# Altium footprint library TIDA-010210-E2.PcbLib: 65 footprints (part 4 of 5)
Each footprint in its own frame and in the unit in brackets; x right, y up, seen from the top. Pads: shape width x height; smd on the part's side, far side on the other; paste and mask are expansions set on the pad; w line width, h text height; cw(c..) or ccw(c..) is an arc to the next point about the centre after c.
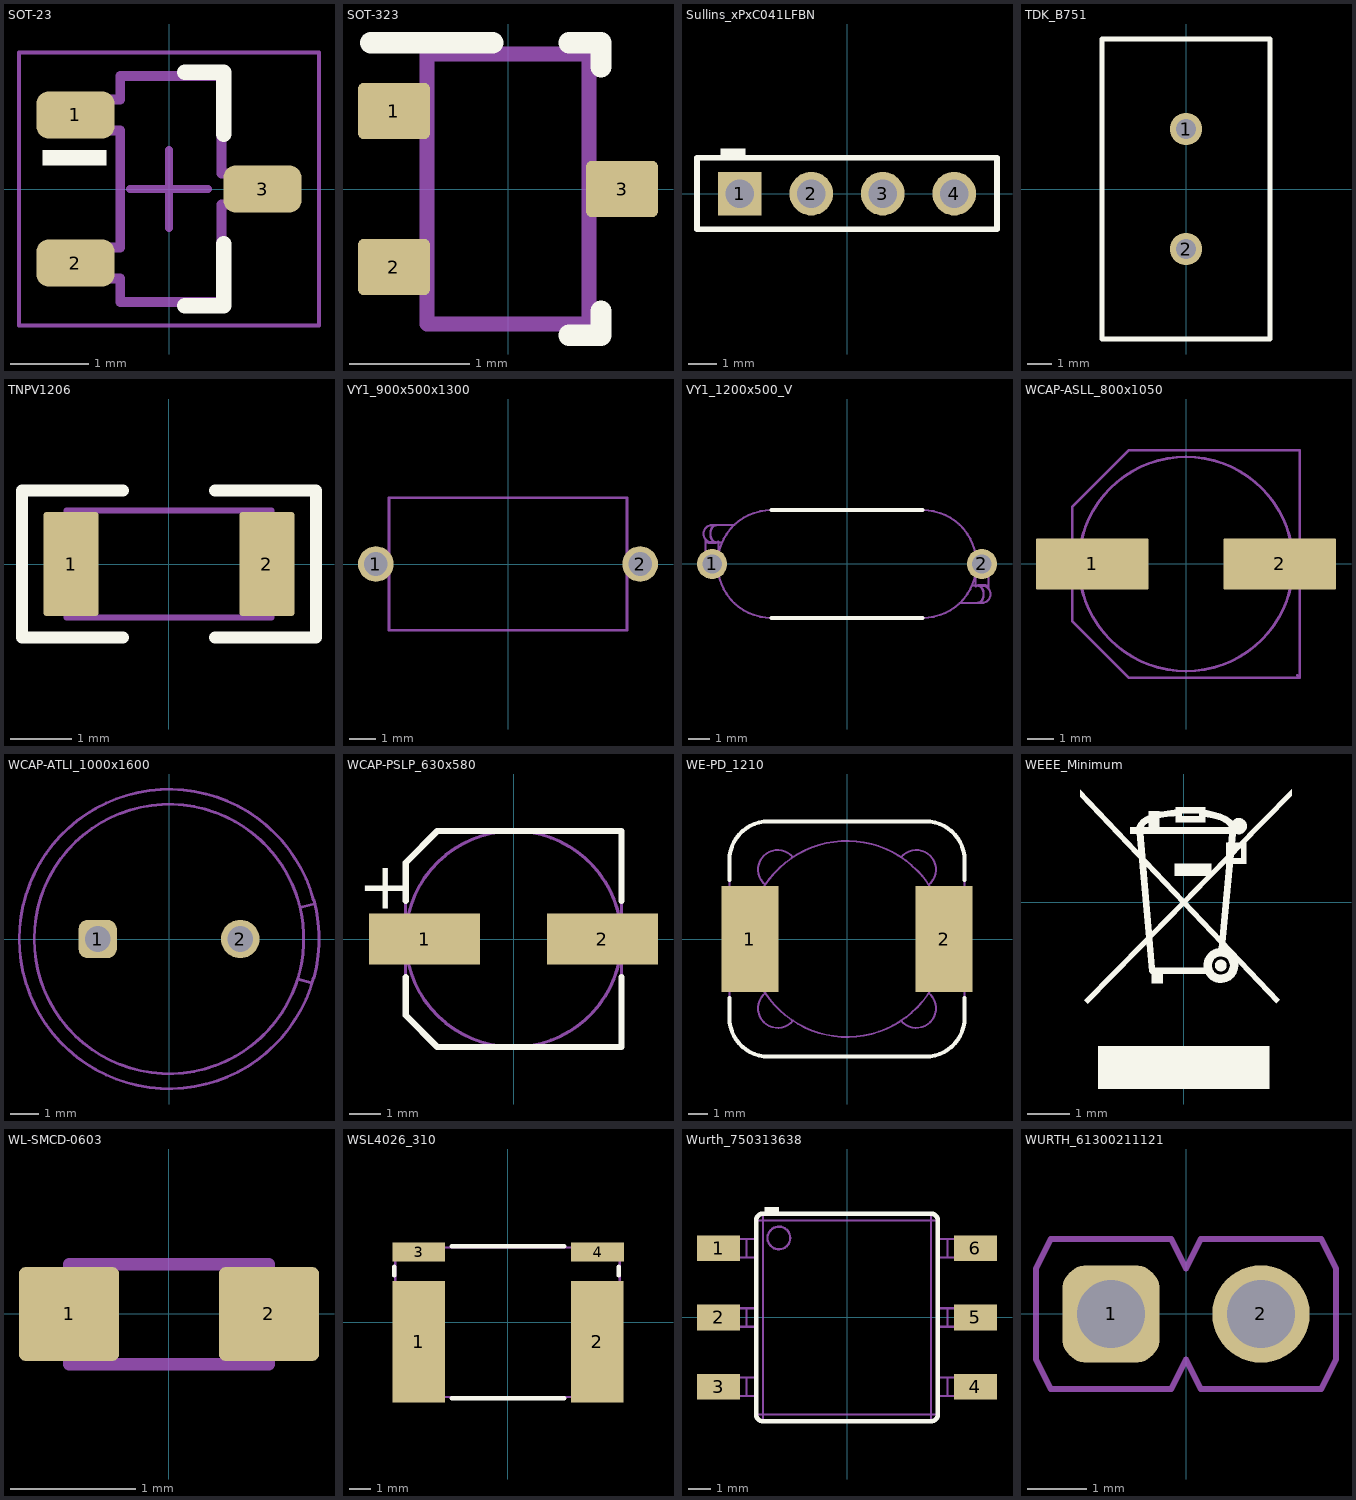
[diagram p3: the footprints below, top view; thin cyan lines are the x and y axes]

## SOT-23 [mm] "SOT23, 3-Leads, Body 2.9x1.3mm, Pitch 0.95mm, Lead Span 2.5mm, IPC Medium Density"
height 1.1
pads (3):
  rrect50% 1x0.6 smd: 1(-1.2,0.95) 2(-1.2,-0.95) 3(1.2,0)
Top Overlay:
  rectangle: -1.625,0.3 -0.8,0.5
  lines w0.2: 0.2,-1.5 0.7,-1.5 0.7,-0.7 ; 0.2,1.5 0.7,1.5 0.7,0.7
Mechanical 5:
  lines w0.127: -1.16,-1.15 -0.625,-1.15 -0.625,-1.45 0.675,-1.45 0.675,-0.2 1.21,-0.2 1.21,0.2 0.675,0.2 0.675,1.45 -0.625,1.45 -0.625,1.15 -1.16,1.15 -1.16,0.75 -0.625,0.75 -0.625,-0.75 -1.16,-0.75 -1.16,-1.15
  text ".Designator" at -0.175,1.225 h0.64
Mechanical 15:
  lines w0.05: -1.925,-1.75 -1.925,1.75 1.925,1.75 1.925,-1.75 -1.925,-1.75
  lines w0.1: -0.5,0 0.5,0 ; 0,-0.5 0,0.5
3D body "SW3dPS-sot-3p290x130ll237h100.STEP": height 1, standoff 0, extent -1.16,-1.45 1.21,1.45

## SOT-323 [mm] "Diodes Inc recommended land pattern.  2016-02-24"
height 1.1
pads (3):
  rrect21% 0.6x0.47 smd: 1(-0.95,0.65) 2(-0.95,-0.65) 3(0.95,0)
Top Overlay:
  lines w0.178: -1.143,1.219 -0.127,1.219 ; 0.508,-1.219 0.775,-1.219 0.775,-1.016 ; 0.508,1.219 0.775,1.219 0.775,1.016
Mechanical 5:
  lines w0.127: -1.125,-0.8 -1.125,-0.5 -0.975,-0.5 -0.935,-0.5 -0.884,-0.5 -0.725,-0.5 -0.675,-0.5 -0.675,-0.8 -0.725,-0.8 -0.884,-0.8 -0.935,-0.8 -0.975,-0.8 -1.125,-0.8 ; -1.125,0.5 -1.125,0.8 -0.975,0.8 -0.935,0.8 -0.884,0.8 -0.725,0.8 -0.675,0.8 -0.675,0.5 -0.725,0.5 -0.884,0.5 -0.935,0.5 -0.975,0.5 -1.125,0.5 ; -0.675,-1.125 -0.675,1.125 0.675,1.125 0.675,-1.125 -0.675,-1.125 ; 0.675,-0.15 0.725,-0.15 0.884,-0.15 0.935,-0.15 0.975,-0.15 1.125,-0.15 1.125,0.15 0.975,0.15 0.935,0.15 0.884,0.15 0.725,0.15 0.675,0.15 0.675,-0.15
  text ".Designator" at -0.25,0.9 h0.8
3D body "SC-70.stp": height 1.13, standoff 0.02, extent -1.125,-1.125 1.125,1.125

## Sullins_xPxC041LFBN [mm] "Receptacle, 2.54mm, 4x1, TH"
height 8.65
pads (4):
  rect 1.55x1.55 hole 1.02: 1(-3.81,0)
  round 1.55 hole 1.02: 2(-1.27,0) 3(1.27,0) 4(3.81,0)
Top Overlay:
  rectangle: -4.5,1.345 -3.6,1.6
  lines w0.2: -5.33,-1.27 -5.33,1.27 5.33,1.27 5.33,-1.27 -5.33,-1.27
Mechanical 5:
  lines w0.1: -5.33,-1.27 5.33,-1.27 5.33,1.27 -5.33,1.27 -5.33,-1.27
  text ".Designator" at -1.6,-0.4 h1.02
3D body "PPTC041LFBN-RC.stp": height 8.5, standoff -3.2, extent -5.33,-1.27 5.33,1.27

## TDK_B751 [mm] "TH, 2-Leads, Dia 12.5mm, Pin Spacing 5mm"
height 16.5
pads (2):
  round 1.35 hole 0.85: 1(0,2.5) 2(0,-2.5)
Top Overlay:
  lines w0.2: -3.5,-6.25 -3.5,6.25 3.5,6.25 3.5,-6.25 -3.5,-6.25
Mechanical 5:
  lines w0.1: -3.5,-6.25 3.5,-6.25 3.5,6.25 -3.5,6.25 -3.5,-6.25
  text ".Designator" at -1.524,-0.508 h1.02
3D body: height 4.4, standoff 3.8, extent -2.849,-2.8 -2.252,-2.203
3D body: height 11.1, standoff 4.1, extent -3.483,-3.485 3.483,3.485
3D body: height 2.9, standoff 2.3, extent -2.848,-2.8 -2.251,-2.203
3D body: height 4.1, standoff 2.6, extent -2.85,-2.8 -2.253,-2.201
3D body: height 4.1, standoff 2.6, extent 2.253,2.201 2.85,2.8
3D body: height 4.4, standoff 3.8, extent 2.252,2.203 2.849,2.8
3D body: height 16.49, standoff 4.01, extent -1.5,-6.201 1.5,6.25
3D body: height 0.3, standoff -0.3, extent -0.297,2.201 0.3,2.799
3D body: height 2.83, standoff -0.21, extent -0.248,2.201 2.791,2.8
3D body: height 2.9, standoff 2.3, extent 2.252,2.203 2.849,2.8
3D body: height 0, standoff -2.5, extent -0.297,2.201 0.3,2.8
3D body: height 7.14, standoff 3.89, extent 2.252,-0.502 2.85,2.75
3D body: height 7.14, standoff 3.89, extent -2.85,-2.75 -2.252,0.502
3D body: height 0, standoff -2.5, extent -0.3,-2.8 0.297,-2.201
3D body: height 2.83, standoff -0.21, extent -2.791,-2.8 0.248,-2.201
3D body: height 0.3, standoff -0.3, extent -0.3,-2.799 0.297,-2.201

## TNPV1206 [mm] "VISHAY"
height 0.65
pads (2):
  rrect11% 0.9x1.7 smd: 1(-1.6,0) 2(1.6,0)
Top Overlay:
  lines w0.2: -0.75,-1.2 -2.4,-1.2 -2.4,1.2 -0.75,1.2 ; 0.75,-1.2 2.4,-1.2 2.4,1.2 0.75,1.2
Mechanical 5:
  lines w0.1: -1.675,-0.875 -1.675,0.875 1.675,0.875 1.675,-0.875 -1.675,-0.875
  text ".Designator" at -1.35,-0.45 h1.5
3D body: height 0.65, standoff 0, extent -1.674,-0.874 -1.101,0.874
3D body: height 0.65, standoff 0, extent -1.099,-0.874 1.099,0.874
3D body: height 0.65, standoff 0, extent 1.101,-0.874 1.674,0.874

## VY1_900x500x1300 [mm] "TH, Body 9x5mm, PinSpacing 10mm"
height 13
pads (2):
  round 1.35 hole 0.9: 1(-5,0) 2(5,0)
Mechanical 5:
  lines w0.1: -4.5,-2.5 -4.5,2.5 4.5,2.5 4.5,-2.5 -4.5,-2.5
  text ".Designator" at -1.8,-0.514 h1.02
3D body "VY1_900x500x1300.stp": height 12.93, standoff -30.07, extent -5.4,-2.5 5.4,2.5

## VY1_1200x500_V [mm] "TH, 2-Leads, Body 12x5mm, Pin Spacing 12.5mm"
height 16
pads (2):
  round 1.4 hole 0.9: 1(-6.25,0) 2(6.25,0)
Top Overlay:
  lines w0.2: -3.5,-2.5 3.5,-2.5 ; -3.5,2.5 3.5,2.5
Mechanical 5:
  drawing of 828 lines, arcs and shapes, not listed
  text ".Designator" at -5.231,-0.83 h1.02
3D body "VY1_1200x500.stp": height 15.99, standoff -20, extent -6.65,-2.5 6.65,2.5

## WCAP-ASLL_800x1050 [mm] "SMD, 2-Leads, Dia 8mm"
height 10.5
pads (2):
  rrect5% 4.2x1.9 smd: 1(-3.5,0) 2(3.5,0)
Mechanical 5:
  circle w0.1: c0,0 r4
  lines w0.1: -4.25,-0.375 -4.3,-0.375 -4.3,0.375 -4.25,0.375 ; 4.15,-4.15 4.25,-4.25 ; 4.25,-0.375 4.3,-0.375 4.3,0.375 4.25,0.375 ; 4.25,-4.25 1.7,-4.25 -1.133,-4.25 -2.125,-4.25 -4.25,-2.125 -4.25,-1.7 -4.25,1.133 -4.25,2.125 -2.125,4.25 -1.133,4.25 1.7,4.25 4.25,4.25 4.25,1.133 4.25,-1.7 4.25,-4.25
  text ".Designator" at -1.724,-0.408 h1.02
3D body "865060653010.stp": height 10.51, standoff 0, extent -4.3,-4.25 4.3,4.25

## WCAP-ATLI_1000x1600 [mm] "TH, 2-Leads, Dia 10mm, Pin Spacing 5mm"
height 17.5
pads (2):
  rrect50% 1.35x1.35 hole 0.9: 1(-2.5,0)
  round 1.35 hole 0.9: 2(2.5,0)
Mechanical 5:
  lines w0.1: 4.5,-1.4 5.017,-1.538 ; 4.6,1.1 5.117,1.238 ; 5.071,-1.359 cw(c0,0) 5.071,1.359 ; 5.081,-1.362 ccw(c0,0) 5.081,1.362 ; 4.564,-1.223 ccw(c0,0) 4.564,1.223 ccw(c0,0) 4.564,-1.223
  text ".Designator" at -1.724,-0.408 h1.02
  text "+" at -6.7,-0.75 h1.5
3D body "860080675015.stp": height 17.51, standoff -4, extent -5.25,-5.248 5.26,5.248

## WCAP-PSLP_630x580 [mm] "SMD, 2-Leads, Dia 6.3mm"
height 5.8
pads (2):
  rect 3.5x1.6 smd: 1(-2.8,0) 2(2.8,0)
Top Overlay:
  lines w0.2: -3.4,-1.2 -3.4,-2.4 -2.4,-3.4 3.4,-3.4 3.4,-1.2 ; -3.4,1.2 -3.4,2.4 -2.4,3.4 3.4,3.4 3.4,1.2
  text "+" at -4.9,0.95 h1.5
Mechanical 5:
  circle w0.1: c0,0 r3.4
  lines w0.1: -3.4,-2.4 -3.4,2.4 -2.4,3.4 3.4,3.4 3.4,-3.4 -2.4,-3.4 -3.4,-2.4
  text "+" at -4.9,0.95 h1.5
  text ".Designator" at -1.524,-0.508 h1.02
3D body: height 1, standoff 0, extent -3.4,-3.4 3.4,3.4
3D body: height 5.81, standoff 5.8, extent 2.404,-2.405 3.401,2.405
3D body: height 5.8, standoff 0.5, extent -3.399,-3.399 3.399,3.399

## WE-PD_1210 [mm] "Wurth Elektronik recommended land pattern"
height 10
pads (2):
  rect 2.9x5.4 smd: 1(-4.95,0) 2(4.95,0)
Top Overlay:
  lines w0.2: -6,-3 -6,-4.003 ccw(c-4,-4.003) -4,-6.003 4,-6.003 ccw(c4,-4.003) 6,-4.003 6,-3 ; -6,3 -6,4.003 cw(c-4,4.003) -4,6.003 4,6.003 cw(c4,4.003) 6,4.003 6,3
Mechanical 5:
  circle w0.1: c0,0.003 r5
  lines w0.1: -4.168,-2.758 ccw(c-3.536,-3.533) -2.761,-4.165 ; -4.168,2.764 cw(c-3.536,3.538) -2.761,4.171 ; 2.761,-4.165 ccw(c3.536,-3.533) 4.168,-2.758 ; 2.761,4.171 cw(c3.536,3.538) 4.168,2.764 ; -6,-3.997 ccw(c-4,-3.997) -4,-5.997 4,-5.997 ccw(c4,-3.997) 6,-3.997 6,4.003 ccw(c4,4.003) 4,6.003 -4,6.003 ccw(c-4,4.003) -6,4.003 -6,-3.997
  text ".Designator" at -2.6,-0.4 h1.85
3D body "WE-PD_1210.stp": height 10.01, standoff 0.01, extent -6,-6 6,6

## WEEE_Minimum [mm] "WEEElie bin"
height 27
Top Overlay:
  drawing of 23 lines, arcs and shapes, not listed

## WL-SMCD-0603 [mm] "SMD, 2-Leads, Body 1.6x0.8mm"
height 0.5
pads (2):
  rrect13% 0.8x0.75 smd: 1(-0.8,0) 2(0.8,0)
Mechanical 5:
  circle w0.1: c-0.659,-0.275 r0.075
  lines w0.1: -0.8,-0.4 -0.8,-0.171 -0.78,-0.171 ccw(c-0.815,0) -0.78,0.171 -0.8,0.171 -0.8,0.4 0.8,0.4 0.8,0.171 0.78,0.171 ccw(c0.815,0) 0.78,-0.171 0.8,-0.171 0.8,-0.4 -0.8,-0.4
  text ".Designator" at -0.4,-0.1 h0.25
3D body "WL-SMCD-0603.stp": height 0.4, standoff 0, extent -0.8,-0.4 0.8,0.4

## WSL4026_310 [mm] "SMD, 4-Leads, Body 6.6x10.14mm"
height 3.1
pads (4):
  rect 2.44x5.6 smd: 1(-4.115,-0.9) 2(4.115,-0.9)
  rect 2.44x0.89 smd: 3(-4.115,3.235) 4(4.135,3.235)
Top Overlay:
  lines w0.2: -5.25,2.15 -5.25,2.55 ; -2.6,-3.5 2.6,-3.5 ; -2.6,3.5 2.6,3.5 ; 5.1,2.15 5.1,2.55
Mechanical 5:
  lines w0.1: -5.2,-3.45 5.15,-3.45 5.15,3.45 -5.2,3.45 -5.2,-3.45
  text ".Designator" at -1.85,-0.6 h1.02
3D body "WSL4026_3100.stp": height 3.1, standoff 0, extent -5.15,-3.25 5.15,3.65

## Wurth_750313638 [mm] "SMD, 6-Leads, Body 8x9.14mm, Pitch 3.05mm"
height 7.62
pads (6):
  rect 1.9x1.14 smd: 1(-5.655,3.05) 2(-5.655,0) 3(-5.655,-3.05) 4(5.655,-3.05) 5(5.655,0) 6(5.655,3.05)
Top Overlay:
  rectangle: -3.625,4.57 -3,4.875
  lines w0.2: -4,-4.27 ccw(c-3.7,-4.27) -3.7,-4.57 3.7,-4.57 ccw(c3.7,-4.27) 4,-4.27 4,4.27 ccw(c3.7,4.27) 3.7,4.57 -3.7,4.57 ccw(c-3.7,4.27) -4,4.27 -4,-4.27
Mechanical 5:
  circle w0.1: c-3,3.5 r0.5
  lines w0.1: -4,-3.455 -4.43,-3.455 ; -4,-2.645 -4.43,-2.645 ; -4,-0.405 -4.43,-0.405 ; -4,0.405 -4.43,0.405 ; -4,2.645 -4.43,2.645 ; -4,3.455 -4.43,3.455 ; 4,-3.455 4.43,-3.455 ; 4,-2.645 4.43,-2.645 ; 4,-0.405 4.43,-0.405 ; 4,0.405 4.43,0.405 ; 4,2.645 4.43,2.645 ; 4,3.455 4.43,3.455 ; -5.47,-3.455 -5.47,-2.645 ; -5.47,-3.455 -6.35,-3.455 -6.35,-2.645 -5.47,-2.645 ; -5.47,-3.455 -5.376,-3.455 ; -5.47,-2.645 -5.376,-2.645 ; -5.47,-0.405 -5.47,0.405 ; -5.47,-0.405 -5.376,-0.405 ; -5.47,-0.405 -6.35,-0.405 -6.35,0.405 -5.47,0.405 ; -5.47,0.405 -5.376,0.405 ; -5.47,2.645 -5.47,3.455 ; -5.47,2.645 -6.35,2.645 -6.35,3.455 -5.47,3.455 ; -5.47,2.645 -5.376,2.645 ; -5.47,3.455 -5.376,3.455 ; -5.376,-3.455 -5.376,-2.645 ; -5.376,-3.455 -4.9,-3.455 ; -5.376,-2.645 -4.9,-2.645 ; -5.376,-0.405 -5.376,0.405 ; -5.376,-0.405 -4.9,-0.405 ; -5.376,0.405 -4.9,0.405 ; -5.376,2.645 -5.376,3.455 ; -5.376,2.645 -4.9,2.645 ; -5.376,3.455 -4.9,3.455 ; -4.9,-3.455 -4.9,-2.645 ; -4.9,-3.455 -4.43,-3.455 ; -4.9,-2.645 -4.43,-2.645 ; -4.9,-0.405 -4.9,0.405 ; -4.9,-0.405 -4.43,-0.405 ; -4.9,0.405 -4.43,0.405 ; -4.9,2.645 -4.9,3.455 ; -4.9,2.645 -4.43,2.645 ; -4.9,3.455 -4.43,3.455 ; -4.43,-3.455 -4.43,-2.645 ; -4.43,-0.405 -4.43,0.405 ; -4.43,2.645 -4.43,3.455 ; -4,-4.27 ccw(c-3.7,-4.27) -3.7,-4.57 ; -4,-4.27 -3.7,-4.27 ; -4,-4.27 -4,4.27 ; -4,4.27 cw(c-3.7,4.27) -3.7,4.57 ; -4,4.27 -3.7,4.27 ; -3.7,-4.57 -3.7,-4.27 ; -3.7,-4.57 3.7,-4.57 ; -3.7,-4.27 3.7,-4.27 ; -3.7,-4.27 -3.7,4.27 ; -3.7,4.27 -3.7,4.57 ; -3.7,4.27 3.7,4.27 ; -3.7,4.57 3.7,4.57 ; 3.7,-4.57 ccw(c3.7,-4.27) 4,-4.27 ; 3.7,-4.57 3.7,-4.27 ; 3.7,-4.27 4,-4.27 ; 3.7,-4.27 3.7,4.27 ; 3.7,4.27 4,4.27 ; 3.7,4.27 3.7,4.57 ; 3.7,4.57 cw(c3.7,4.27) 4,4.27 ; 4,-4.27 4,4.27 ; 4.43,-3.455 4.43,-2.645 ; 4.43,-3.455 4.9,-3.455 ; 4.43,-2.645 4.9,-2.645 ; 4.43,-0.405 4.43,0.405 ; 4.43,-0.405 4.9,-0.405 ; 4.43,0.405 4.9,0.405 ; 4.43,2.645 4.43,3.455 ; 4.43,2.645 4.9,2.645 ; 4.43,3.455 4.9,3.455 ; 4.9,-3.455 4.9,-2.645 ; 4.9,-3.455 5.376,-3.455 ; 4.9,-2.645 5.376,-2.645 ; 4.9,-0.405 4.9,0.405 ; 4.9,-0.405 5.376,-0.405 ; 4.9,0.405 5.376,0.405 ; 4.9,2.645 4.9,3.455 ; 4.9,2.645 5.376,2.645 ; 4.9,3.455 5.376,3.455 ; 5.376,-3.455 5.376,-2.645 ; 5.376,-3.455 5.47,-3.455 ; 5.376,-2.645 5.47,-2.645 ; 5.376,-0.405 5.376,0.405 ; 5.376,-0.405 5.47,-0.405 ; 5.376,0.405 5.47,0.405 ; 5.376,2.645 5.376,3.455 ; 5.376,2.645 5.47,2.645 ; 5.376,3.455 5.47,3.455 ; 5.47,-3.455 5.47,-2.645 ; 5.47,-3.455 6.35,-3.455 6.35,-2.645 5.47,-2.645 ; 5.47,-0.405 5.47,0.405 ; 5.47,-0.405 6.35,-0.405 6.35,0.405 5.47,0.405 ; 5.47,2.645 5.47,3.455 ; 5.47,2.645 6.35,2.645 6.35,3.455 5.47,3.455
  text ".Designator" at -1.524,-0.508 h1.02
3D body "750313638.stp": height 7.62, standoff 0, extent -6.35,-4.57 6.35,4.57

## WURTH_61300211121 [mm] "Header, 2.54mm, 2x1, TH"
height 8.89
pads (2):
  rrect50% 1.65x1.65 hole 1.15: 1(-1.27,0)
  round 1.65 hole 1.15: 2(1.27,0)
Mechanical 5:
  lines w0.1: -2.54,-0.77 -2.54,0.77 -2.29,1.27 -0.25,1.27 0,0.77 0.25,1.27 2.29,1.27 2.54,0.77 2.54,-0.77 2.29,-1.27 0.25,-1.27 0,-0.77 -0.25,-1.27 -2.29,-1.27 -2.54,-0.77
  text ".Designator" at -1.524,-0.508 h1.02
3D body "61300211121.stp": height 8.54, standoff -3, extent -2.54,-1.27 2.54,1.27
